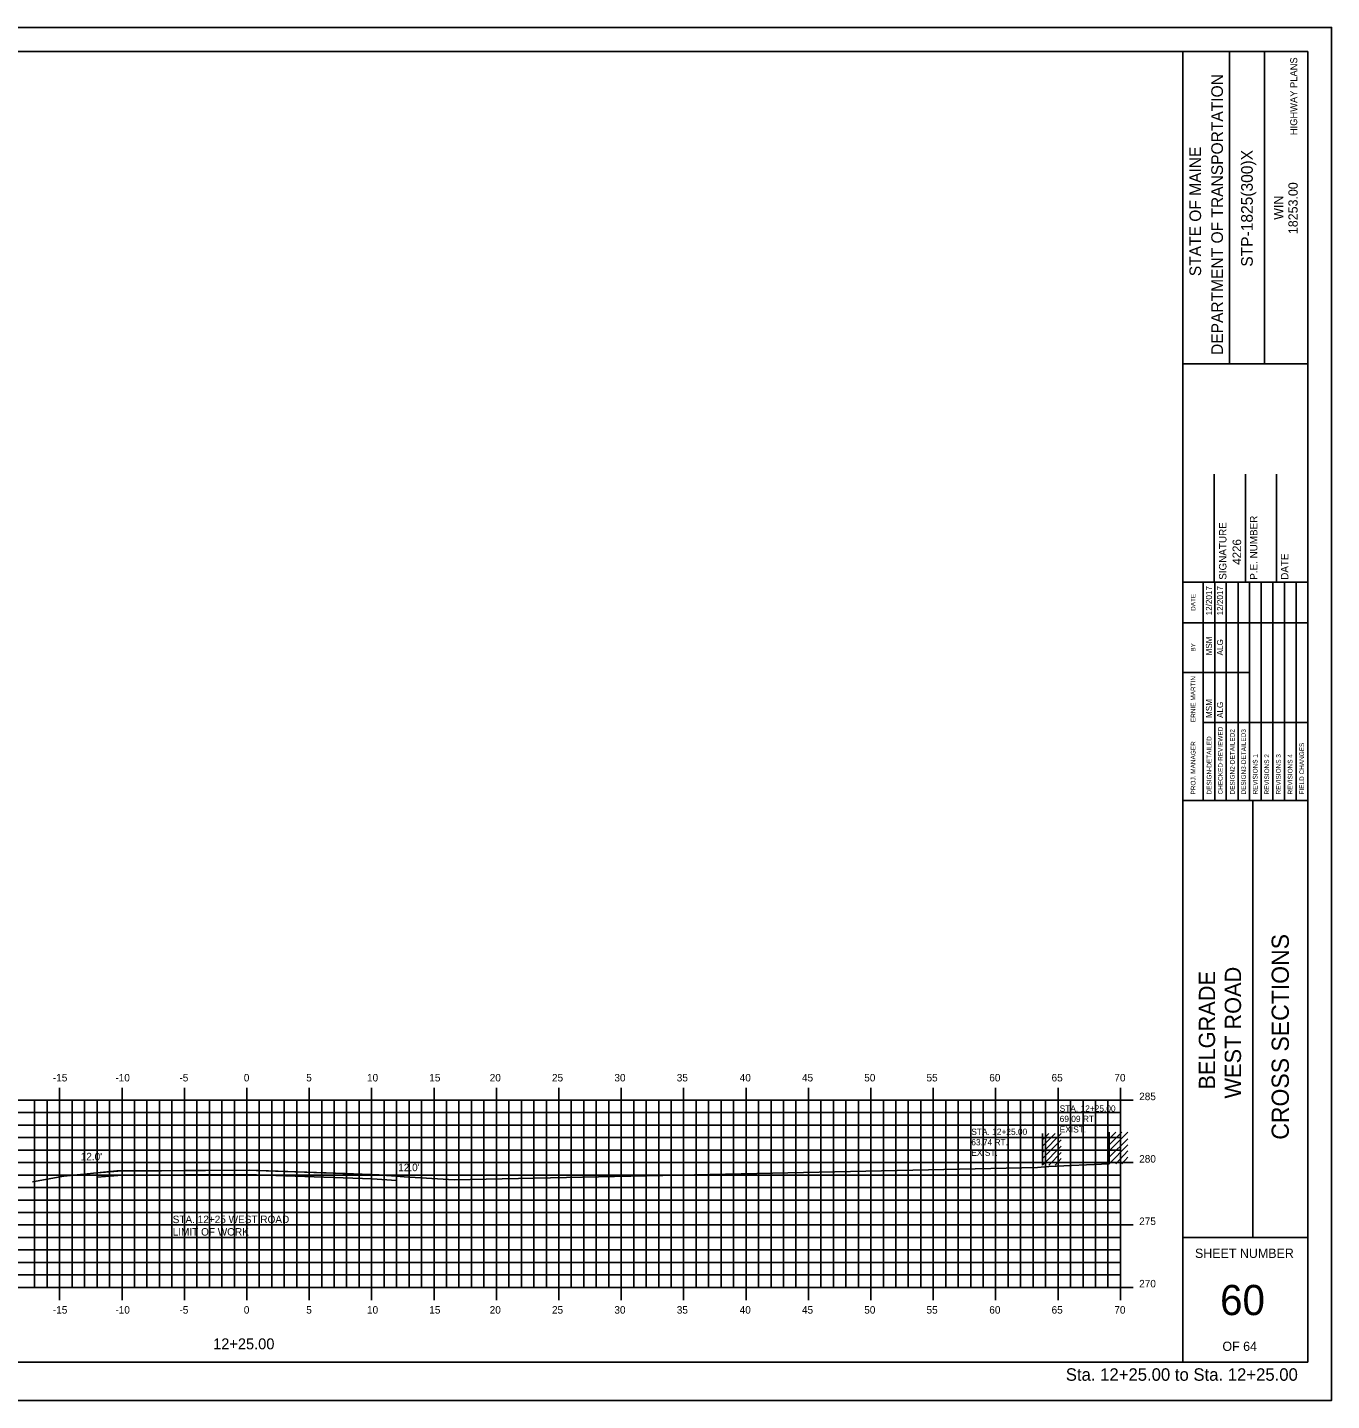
# Model space of a CAD drawing. Extents: x 850898 to 851068, y 366543 to 366653.
# Drawn here: x 850963.9 to 851068.4, y 366542.9 to 366652.9 of the extents above; entities that cross this region are included whole.
import ezdxf

# ---------------------------------------------------------------- set-up
doc = ezdxf.new("R2010")
doc.units = 0
for name, color, linetype in [('ANNOTATION', 7, 'Continuous'), ('BORDER', 7, 'Continuous'), ('D_Roadway_Edge_TW', 7, 'Continuous'), ('D_Roadway_SubGrade', 7, 'Continuous'), ('D_Text_Monospaced', 7, 'Continuous'), ('D_Text_Standard', 7, 'Continuous'), ('H_V ANNOTATION', 7, 'Continuous'), ('HIGHWAY_TITLE', 7, 'Continuous'), ('MAJOR', 7, 'Continuous'), ('MINOR', 7, 'Continuous'), ('PLOT BOUNDARY', 7, 'Continuous'), ('S_Buildings', 7, 'Continuous'), ('S_Buildings_Attachments', 7, 'Continuous'), ('S_Roadway_Centerline', 7, 'Continuous')]:
    doc.layers.add(name, color=color, linetype=linetype)

msp = doc.modelspace()

# ---------------------------------------------------------------- linework, layer by layer
at = {"layer": 'BORDER'}
for p, q in [((851066.48, 366650.99), (850906.48, 366650.99)), ((851056.48, 366545.99), (851056.48, 366650.99)), ((851060.2, 366625.98), (851060.2, 366650.98)), ((851063, 366625.98), (851063, 366650.98)), ((851066.48, 366545.99), (851066.48, 366650.99)), ((851056.48, 366625.98), (851066.48, 366625.98)), ((851058.98, 366608.49), (851058.98, 366617.14)), ((851061.48, 366608.49), (851061.48, 366617.14)), ((851063.98, 366608.49), (851063.98, 366617.14)), ((851056.48, 366608.49), (851066.48, 366608.49)), ((851056.48, 366590.99), (851066.48, 366590.99)), ((851062.07, 366555.99), (851062.07, 366590.99)), ((851056.48, 366555.99), (851066.48, 366555.99)), ((850906.48, 366545.99), (851066.48, 366545.99))]:
    msp.add_line(p, q, dxfattribs=at)
for points in [[(851058.09, 366605.24), (851058.09, 366608.49)], [(851059.02, 366590.99), (851059.02, 366608.49)], [(851059.95, 366608.49), (851059.95, 366590.99)], [(851060.89, 366590.99), (851060.89, 366608.49)], [(851061.82, 366590.99), (851061.82, 366608.49)], [(851062.75, 366590.99), (851062.75, 366608.49)], [(851063.68, 366590.99), (851063.68, 366608.49)], [(851064.61, 366590.99), (851064.61, 366608.49)], [(851065.54, 366590.99), (851065.54, 366608.49)], [(851058.09, 366590.99), (851058.09, 366607.78)], [(851056.48, 366605.24), (851066.48, 366605.24)], [(851056.48, 366601.24), (851058.09, 366601.24)], [(851058.09, 366601.24), (851061.82, 366601.24)], [(851058.09, 366597.24), (851066.48, 366597.24)]]:
    msp.add_lwpolyline(points, dxfattribs=at)
at = {"layer": 'D_Roadway_Edge_TW'}
for p, q in [((850971.47, 366561.32), (850969.47, 366561.16)), ((850971.47, 366560.99), (850969.47, 366560.83)), ((850981.47, 366561.37), (850971.47, 366561.32)), ((850981.48, 366561.04), (850971.47, 366560.99)), ((850991.51, 366560.7), (850981.46, 366561.04)), ((850991.47, 366561.04), (850981.47, 366561.37)), ((850991.47, 366561.04), (850993.47, 366560.89)), ((850991.51, 366560.7), (850993.47, 366560.56))]:
    msp.add_line(p, q, dxfattribs=at)
at = {"layer": 'D_Roadway_SubGrade'}
for p, q in [((850969.47, 366560.83), (850969.47, 366561.16)), ((850971.47, 366560.99), (850971.47, 366561.32)), ((850991.47, 366560.7), (850991.47, 366561.04)), ((850993.47, 366560.56), (850993.47, 366560.89))]:
    msp.add_line(p, q, dxfattribs=at)
at = {"layer": 'MAJOR'}
for p, q in [((850966.47, 366567.99), (850966.47, 366566.99)), ((850971.47, 366567.99), (850971.47, 366566.99)), ((850976.47, 366567.99), (850976.47, 366566.99)), ((850981.47, 366567.99), (850981.47, 366566.99)), ((850986.47, 366567.99), (850986.47, 366566.99)), ((850991.47, 366567.99), (850991.47, 366566.99)), ((850996.47, 366567.99), (850996.47, 366566.99)), ((851001.47, 366567.99), (851001.47, 366566.99)), ((851006.47, 366567.99), (851006.47, 366566.99)), ((851011.47, 366567.99), (851011.47, 366566.99)), ((851016.47, 366567.99), (851016.47, 366566.99)), ((851021.47, 366567.99), (851021.47, 366566.99)), ((851026.47, 366567.99), (851026.47, 366566.99)), ((851031.47, 366567.99), (851031.47, 366566.99)), ((851036.47, 366567.99), (851036.47, 366566.99)), ((851041.47, 366567.99), (851041.47, 366566.99)), ((851046.47, 366567.99), (851046.47, 366566.99)), ((851051.47, 366567.99), (851051.47, 366566.99)), ((850911.47, 366566.99), (851051.47, 366566.99)), ((850911.47, 366566.99), (851051.47, 366566.99)), ((850966.47, 366551.99), (850966.47, 366566.99)), ((850971.47, 366551.99), (850971.47, 366566.99)), ((850976.47, 366551.99), (850976.47, 366566.99)), ((850981.47, 366551.99), (850981.47, 366566.99)), ((850986.47, 366551.99), (850986.47, 366566.99)), ((850991.47, 366551.99), (850991.47, 366566.99)), ((850996.47, 366551.99), (850996.47, 366566.99)), ((851001.47, 366551.99), (851001.47, 366566.99)), ((851006.47, 366551.99), (851006.47, 366566.99)), ((851011.47, 366551.99), (851011.47, 366566.99)), ((851016.47, 366551.99), (851016.47, 366566.99)), ((851021.47, 366551.99), (851021.47, 366566.99)), ((851026.47, 366551.99), (851026.47, 366566.99)), ((851031.47, 366551.99), (851031.47, 366566.99)), ((851036.47, 366551.99), (851036.47, 366566.99)), ((851041.47, 366551.99), (851041.47, 366566.99)), ((851046.47, 366551.99), (851046.47, 366566.99)), ((851052.48, 366566.99), (851050.47, 366566.99)), ((851051.47, 366551.99), (851051.47, 366566.99)), ((851051.47, 366551.99), (851051.47, 366566.99)), ((850911.47, 366561.99), (851051.47, 366561.99)), ((851052.48, 366561.99), (851050.47, 366561.99)), ((850911.47, 366556.99), (851051.47, 366556.99)), ((851052.48, 366556.99), (851050.47, 366556.99)), ((850911.47, 366551.99), (851051.47, 366551.99)), ((850911.47, 366551.99), (851051.47, 366551.99)), ((850966.47, 366550.98), (850966.47, 366551.99)), ((850971.47, 366550.98), (850971.47, 366551.99)), ((850976.47, 366550.98), (850976.47, 366551.99)), ((850981.47, 366550.98), (850981.47, 366551.99)), ((850986.47, 366550.98), (850986.47, 366551.99)), ((850991.47, 366550.98), (850991.47, 366551.99)), ((850996.47, 366550.98), (850996.47, 366551.99)), ((851001.47, 366550.98), (851001.47, 366551.99)), ((851006.47, 366550.98), (851006.47, 366551.99)), ((851011.47, 366550.98), (851011.47, 366551.99)), ((851016.47, 366550.98), (851016.47, 366551.99)), ((851021.47, 366550.98), (851021.47, 366551.99)), ((851026.47, 366550.98), (851026.47, 366551.99)), ((851031.47, 366550.98), (851031.47, 366551.99)), ((851036.47, 366550.98), (851036.47, 366551.99)), ((851041.47, 366550.98), (851041.47, 366551.99)), ((851046.47, 366550.98), (851046.47, 366551.99)), ((851052.48, 366551.99), (851050.47, 366551.99)), ((851051.47, 366550.98), (851051.47, 366551.99))]:
    msp.add_line(p, q, dxfattribs=at)
at = {"layer": 'MINOR'}
for p, q in [((850964.47, 366551.99), (850964.47, 366566.99)), ((850965.47, 366551.99), (850965.47, 366566.99)), ((850967.47, 366551.99), (850967.47, 366566.99)), ((850968.47, 366551.99), (850968.47, 366566.99)), ((850969.47, 366551.99), (850969.47, 366566.99)), ((850970.47, 366551.99), (850970.47, 366566.99)), ((850972.47, 366551.99), (850972.47, 366566.99)), ((850973.47, 366551.99), (850973.47, 366566.99)), ((850974.47, 366551.99), (850974.47, 366566.99)), ((850975.47, 366551.99), (850975.47, 366566.99)), ((850977.47, 366551.99), (850977.47, 366566.99)), ((850978.47, 366551.99), (850978.47, 366566.99)), ((850979.47, 366551.99), (850979.47, 366566.99)), ((850980.47, 366551.99), (850980.47, 366566.99)), ((850982.47, 366551.99), (850982.47, 366566.99)), ((850983.47, 366551.99), (850983.47, 366566.99)), ((850984.47, 366551.99), (850984.47, 366566.99)), ((850985.47, 366551.99), (850985.47, 366566.99)), ((850987.47, 366551.99), (850987.47, 366566.99)), ((850988.47, 366551.99), (850988.47, 366566.99)), ((850989.47, 366551.99), (850989.47, 366566.99)), ((850990.47, 366551.99), (850990.47, 366566.99)), ((850992.47, 366551.99), (850992.47, 366566.99)), ((850993.47, 366551.99), (850993.47, 366566.99)), ((850994.47, 366551.99), (850994.47, 366566.99)), ((850995.47, 366551.99), (850995.47, 366566.99)), ((850997.47, 366551.99), (850997.47, 366566.99)), ((850998.47, 366551.99), (850998.47, 366566.99)), ((850999.47, 366551.99), (850999.47, 366566.99)), ((851000.47, 366551.99), (851000.47, 366566.99)), ((851002.47, 366551.99), (851002.47, 366566.99)), ((851003.47, 366551.99), (851003.47, 366566.99)), ((851004.47, 366551.99), (851004.47, 366566.99)), ((851005.47, 366551.99), (851005.47, 366566.99)), ((851007.47, 366551.99), (851007.47, 366566.99)), ((851008.47, 366551.99), (851008.47, 366566.99)), ((851009.47, 366551.99), (851009.47, 366566.99)), ((851010.47, 366551.99), (851010.47, 366566.99)), ((851012.47, 366551.99), (851012.47, 366566.99)), ((851013.47, 366551.99), (851013.47, 366566.99)), ((851014.47, 366551.99), (851014.47, 366566.99)), ((851015.47, 366551.99), (851015.47, 366566.99)), ((851017.47, 366551.99), (851017.47, 366566.99)), ((851018.47, 366551.99), (851018.47, 366566.99)), ((851019.47, 366551.99), (851019.47, 366566.99)), ((851020.47, 366551.99), (851020.47, 366566.99)), ((851022.47, 366551.99), (851022.47, 366566.99)), ((851023.47, 366551.99), (851023.47, 366566.99)), ((851024.47, 366551.99), (851024.47, 366566.99)), ((851025.47, 366551.99), (851025.47, 366566.99)), ((851027.47, 366551.99), (851027.47, 366566.99)), ((851028.47, 366551.99), (851028.47, 366566.99)), ((851029.47, 366551.99), (851029.47, 366566.99)), ((851030.47, 366551.99), (851030.47, 366566.99)), ((851032.47, 366551.99), (851032.47, 366566.99)), ((851033.47, 366551.99), (851033.47, 366566.99)), ((851034.47, 366551.99), (851034.47, 366566.99)), ((851035.47, 366551.99), (851035.47, 366566.99)), ((851037.47, 366551.99), (851037.47, 366566.99)), ((851038.47, 366551.99), (851038.47, 366566.99)), ((851039.47, 366551.99), (851039.47, 366566.99)), ((851040.47, 366551.99), (851040.47, 366566.99)), ((851042.47, 366551.99), (851042.47, 366566.99)), ((851043.47, 366551.99), (851043.47, 366566.99)), ((851044.47, 366551.99), (851044.47, 366566.99)), ((851045.47, 366551.99), (851045.47, 366566.99)), ((851047.47, 366551.99), (851047.47, 366566.99)), ((851048.47, 366551.99), (851048.47, 366566.99)), ((851049.47, 366551.99), (851049.47, 366566.99)), ((851050.47, 366551.99), (851050.47, 366566.99)), ((850911.47, 366565.99), (851051.47, 366565.99)), ((851051.47, 366565.99), (851050.47, 366565.99)), ((850911.47, 366564.99), (851051.47, 366564.99)), ((851051.47, 366564.99), (851050.47, 366564.99)), ((850911.47, 366563.99), (851051.47, 366563.99)), ((850911.47, 366562.99), (851051.47, 366562.99)), ((851051.47, 366563.99), (851050.47, 366563.99)), ((851051.47, 366562.99), (851050.47, 366562.99)), ((850911.47, 366560.99), (851051.47, 366560.99)), ((851051.47, 366560.99), (851050.47, 366560.99)), ((850911.47, 366559.99), (851051.47, 366559.99)), ((851051.47, 366559.99), (851050.47, 366559.99)), ((850911.47, 366558.99), (851051.47, 366558.99)), ((851051.47, 366558.99), (851050.47, 366558.99)), ((850911.47, 366557.99), (851051.47, 366557.99)), ((851051.47, 366557.99), (851050.47, 366557.99)), ((850911.47, 366555.99), (851051.47, 366555.99)), ((851051.47, 366555.99), (851050.47, 366555.99)), ((850911.47, 366554.99), (851051.47, 366554.99)), ((851051.47, 366554.99), (851050.47, 366554.99)), ((850911.47, 366553.99), (851051.47, 366553.99)), ((851051.47, 366553.99), (851050.47, 366553.99)), ((850911.47, 366552.99), (851051.47, 366552.99)), ((851051.47, 366552.99), (851050.47, 366552.99))]:
    msp.add_line(p, q, dxfattribs=at)
at = {"layer": 'PLOT BOUNDARY'}
msp.add_lwpolyline([(850898.38, 366542.93), (851068.38, 366542.93), (851068.38, 366652.93), (850898.38, 366652.93)], close=True, dxfattribs=at)
at = {"layer": 'S_Buildings'}
for p, q in [((851050.56, 366561.9), (851050.56, 366564.43)), ((851050.56, 366562.92), (851052.07, 366564.43)), ((851050.56, 366563.41), (851051.58, 366564.43)), ((851050.56, 366563.9), (851051.09, 366564.43)), ((851050.56, 366562.43), (851052.07, 366563.9)), ((851050.56, 366561.9), (851052.07, 366563.41)), ((851051.09, 366561.9), (851052.07, 366562.92)), ((851051.58, 366561.9), (851052.07, 366562.43))]:
    msp.add_line(p, q, dxfattribs=at)
at = {"layer": 'S_Buildings_Attachments'}
for p, q in [((851045.21, 366561.79), (851045.21, 366564.32)), ((851045.21, 366562.81), (851046.72, 366564.32)), ((851045.21, 366563.3), (851046.23, 366564.32)), ((851045.21, 366563.8), (851045.74, 366564.32)), ((851045.21, 366562.32), (851046.72, 366563.8)), ((851045.21, 366561.79), (851046.72, 366563.3)), ((851045.74, 366561.79), (851046.72, 366562.81)), ((851046.23, 366561.79), (851046.72, 366562.32))]:
    msp.add_line(p, q, dxfattribs=at)
at = {"layer": 'S_Roadway_Centerline'}
msp.add_lwpolyline([(850964.31, 366560.46), (850966.82, 366560.89), (850971.06, 366561.32), (850974.64, 366561.32), (850981.69, 366561.38), (850989.35, 366561.11), (850992.08, 366561.01), (850994.08, 366560.84), (850998.09, 366560.61), (851016.09, 366560.99), (851044.83, 366561.6), (851045.74, 366561.68), (851050.56, 366561.9)], dxfattribs=at)

# ---------------------------------------------------------------- texts
at = {"layer": 'ANNOTATION'}
msp.add_text('4226', height=0.69, rotation=90, dxfattribs=at).set_placement((851061.14, 366609.88))
for s, p in [('STA. 12+25 WEST ROAD', (850975.53, 366557.14)), ('LIMIT OF WORK', (850975.53, 366556.14))]:
    msp.add_text(s, height=0.6, dxfattribs=at).set_placement(p)
at = {"layer": 'BORDER'}
for s, height, rotation, p in [('DEPARTMENT OF TRANSPORTATION', 0.9318, 90, (851059.68, 366626.69)), ('STATE OF MAINE', 0.9318, 90, (851057.93, 366633)), ('STP-1825(300)X', 0.9318, 90, (851062.07, 366633.76)), ('18253.00', 0.745, 90, (851065.67, 366636.37)), ('WIN', 0.745, 90, (851064.51, 366637.52)), ('P.E. NUMBER', 0.5906, 90, (851062.44, 366608.68)), ('SIGNATURE', 0.591, 90, (851059.96, 366608.68)), ('DATE', 0.591, 90, (851064.92, 366608.68)), ('12/2017', 0.485, 90, (851058.8, 366605.83)), ('12/2017', 0.485, 90, (851059.69, 366605.83)), ('DATE', 0.371, 90, (851057.48, 366606.19)), ('MSM', 0.485, 90, (851058.8, 366602.62)), ('ALG', 0.485, 90, (851059.69, 366602.62)), ('BY', 0.371, 90, (851057.48, 366602.92)), ('ERNIE MARTIN', 0.3727, 90, (851057.48, 366597.28)), ('MSM', 0.485, 90, (851058.8, 366597.61)), ('ALG', 0.485, 90, (851059.69, 366597.61)), ('DESIGN-DETAILED', 0.3727, 90, (851058.76, 366591.48)), ('CHECKED-REVIEWED', 0.3727, 90, (851059.66, 366591.48)), ('DESIGN2-DETAILED2', 0.3727, 90, (851060.62, 366591.48)), ('DESIGN3-DETAILED3', 0.3727, 90, (851061.52, 366591.48)), ('PROJ. MANAGER', 0.3727, 90, (851057.48, 366591.48)), ('FIELD CHANGES', 0.3727, 90, (851066.18, 366591.48)), ('REVISIONS 1', 0.3727, 90, (851062.45, 366591.48)), ('REVISIONS 2', 0.3727, 90, (851063.38, 366591.48)), ('REVISIONS 3', 0.3727, 90, (851064.31, 366591.48)), ('REVISIONS 4', 0.3727, 90, (851065.25, 366591.48)), ('CROSS SECTIONS', 1.3779, 90, (851064.96, 366563.82)), ('SHEET NUMBER', 0.7453, 360, (851057.44, 366554.35)), ('60', 2.419, 360, (851059.45, 366549.77)), ('OF 64', 0.745, 360, (851059.64, 366546.9))]:
    msp.add_text(s, height=height, rotation=rotation, dxfattribs=at).set_placement(p)
at = {"layer": 'D_Text_Monospaced'}
for s, p in [('STA. 12+25.00', (851046.6, 366566.07)), ('69.09 RT.', (851046.6, 366565.24)), ('STA. 12+25.00', (851039.52, 366564.21)), ('EXIST. ', (851046.6, 366564.4)), ('63.74 RT.', (851039.52, 366563.37)), ('EXIST. ', (851039.52, 366562.53))]:
    msp.add_text(s, height=0.5, dxfattribs=at).set_placement(p)
at = {"layer": 'D_Text_Standard'}
for p in [(850968.16, 366562.17), (850993.6, 366561.3)]:
    msp.add_text("12.0'", height=0.6, dxfattribs=at).set_placement(p)
at = {"layer": 'H_V ANNOTATION'}
for s, height, p in [('-15', 0.6, (850965.93, 366568.49)), ('-10', 0.6, (850970.94, 366568.49)), ('-5', 0.6, (850976.07, 366568.49)), ('0', 0.6, (850981.23, 366568.49)), ('5', 0.6, (850986.23, 366568.49)), ('10', 0.6, (850991.1, 366568.49)), ('15', 0.6, (850996.09, 366568.49)), ('20', 0.6, (851000.93, 366568.49)), ('25', 0.6, (851005.92, 366568.49)), ('30', 0.6, (851010.92, 366568.49)), ('35', 0.6, (851015.92, 366568.49)), ('40', 0.6, (851020.96, 366568.49)), ('45', 0.6, (851025.95, 366568.49)), ('50', 0.6, (851030.94, 366568.49)), ('55', 0.6, (851035.93, 366568.49)), ('60', 0.6, (851040.96, 366568.49)), ('65', 0.6, (851045.95, 366568.49)), ('70', 0.6, (851050.98, 366568.49)), ('285', 0.6, (851052.97, 366566.99)), ('280', 0.6, (851052.97, 366561.99)), ('275', 0.6, (851052.97, 366556.99)), ('270', 0.6, (851052.97, 366551.99)), ('-15', 0.6, (850965.93, 366549.89)), ('-10', 0.6, (850970.94, 366549.89)), ('-5', 0.6, (850976.07, 366549.89)), ('0', 0.6, (850981.23, 366549.89)), ('5', 0.6, (850986.23, 366549.89)), ('10', 0.6, (850991.1, 366549.89)), ('15', 0.6, (850996.09, 366549.89)), ('20', 0.6, (851000.93, 366549.89)), ('25', 0.6, (851005.92, 366549.89)), ('30', 0.6, (851010.92, 366549.89)), ('35', 0.6, (851015.92, 366549.89)), ('40', 0.6, (851020.96, 366549.89)), ('45', 0.6, (851025.95, 366549.89)), ('50', 0.6, (851030.94, 366549.89)), ('55', 0.6, (851035.93, 366549.89)), ('60', 0.6, (851040.96, 366549.89)), ('65', 0.6, (851045.95, 366549.89)), ('70', 0.6, (851050.98, 366549.89)), ('12+25.00', 0.875, (850978.77, 366547.03)), ('Sta. 12+25.00 to Sta. 12+25.00', 1.0002, (851047.09, 366544.51))]:
    msp.add_text(s, height=height, dxfattribs=at).set_placement(p)
at = {"layer": 'HIGHWAY_TITLE'}
for s, height, p in [('HIGHWAY PLANS', 0.559, (851065.63, 366644.3)), ('BELGRADE', 1.304, (851059.05, 366567.84)), ('WEST ROAD', 1.304, (851061.13, 366567.12))]:
    msp.add_text(s, height=height, rotation=90, dxfattribs=at).set_placement(p)
at = {"layer": 'S_Roadway_Centerline'}
for s, p in [('C', (850981.69, 366561.38)), ('L', (850981.69, 366561.37))]:
    msp.add_text(s, height=0.0146, dxfattribs=at).set_placement(p)

doc.saveas('drawing.dxf')
